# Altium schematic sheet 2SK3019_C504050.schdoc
size 127 x 101 mm
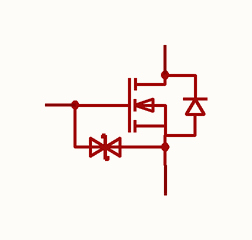
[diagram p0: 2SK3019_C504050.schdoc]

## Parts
Q?  2sk3019_c504050  [SOT-523-3_L1.6-W0.8-P0.50-LS1.6-BR]  (value not drawn)

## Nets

Not connected (* = marked no-connect by the designer): Q? 1(G) 2(S) 3(D)

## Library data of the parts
Q? = 2sk3019_c504050: 数量:1个N沟道;漏源电压(Vdss):30V;连续漏极电流(Id):100mA;导通电阻(RDS(on)):3.8Ω@4V；6Ω@2.5V;耗散功率(Pd):150mW;阈值电压(Vgs(th)):1.5V;; Manufacturer: CJ(江苏长电/长晶); AddInBom: yes; ModelId: 52d9edd53d874f49a5800237040977fe; ModelTransform: 57.0865,66.929,0,0,0,0,0,0,0; Number: 1个N沟道; Drain to Source Voltage: 30V; Current - Continuous Drain(Id): 100mA; Pd - Power Dissipation: 150mW; Gate Threshold Voltage (Vgs(th)): 1.5V; Input Capacitance(Ciss): 13pF; Reverse Transfer Capacitance (Crss@Vds): 4pF; Type: N沟道; Output Capacitance(Coss): 9pF; Vgs: ±20V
